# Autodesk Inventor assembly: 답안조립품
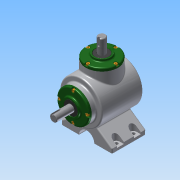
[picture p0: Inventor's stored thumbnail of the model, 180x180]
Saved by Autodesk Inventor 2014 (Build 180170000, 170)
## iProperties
Created: 2017-04
Part Number: 답안조립품
Document SubType Name: Assembly
Designer: NET
Author: NET
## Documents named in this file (14)
- C:\Users\NET\Desktop\따오기\답안조립품.iam
- C:\Users\NET\Desktop\따오기\답안도면.ipt
- C:\Users\NET\Desktop\따오기\메인 베벨기어.ipt
- C:\Users\NET\Desktop\따오기\메인 축.ipt
- 메인 축.ipt
- C:\Users\NET\Desktop\따오기\베어링 6203.ipt
- C:\Users\NET\Desktop\따오기\볼트 M4.ipt
- C:\Users\NET\Desktop\따오기\서브 베벨기어.ipt
- C:\Users\NET\Desktop\따오기\서브 축.ipt
- 서브 축.ipt
- C:\Users\NET\Desktop\따오기\오일실 17 32 8.ipt
- C:\Users\NET\Desktop\따오기\커버.ipt
- C:\Users\NET\Desktop\따오기\키 4x4.ipt
- C:\Users\NET\Desktop\따오기\키 5x5.ipt
## Named parameters: d14_d13 = 0
